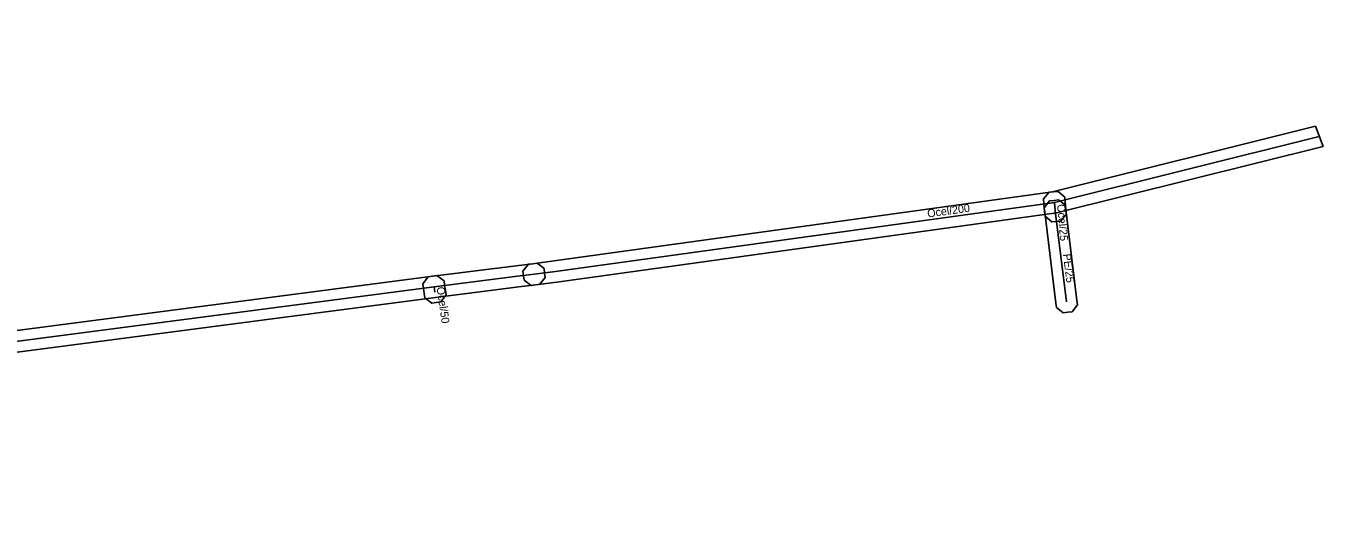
# Model space of a CAD drawing. Extents: x -866668 to -866425, y -1041329 to -1040263.
# Drawn here: x -866546.2 to -866424.6, y -1040308.7 to -1040263.2 of the extents above; entities that cross this region are included whole.
import ezdxf

# ---------------------------------------------------------------- set-up
doc = ezdxf.new("R2010")
doc.units = 0
for name, color, linetype in [('1', 7, 'Continuous'), ('24', 7, 'Continuous'), ('30', 7, 'Continuous')]:
    doc.layers.add(name, color=color, linetype=linetype)

msp = doc.modelspace()

# ---------------------------------------------------------------- linework, layer by layer
at = {"layer": '1'}
for points in [[(-866449.99, -1040278.77), (-866425.36, -1040272.63), (-866424.65, -1040274.51), (-866449.61, -1040280.73), (-866496.43, -1040287.21), (-866498.43, -1040287.47), (-866498.84, -1040287.53), (-866499.5, -1040287.02), (-866499.55, -1040286.61), (-866499.6, -1040286.2), (-866499.1, -1040285.54), (-866498.69, -1040285.49), (-866496.69, -1040285.23)], [(-866448.84, -1040279.25), (-866448.8, -1040279.66), (-866448.73, -1040280.46), (-866448.7, -1040280.88), (-866449.23, -1040281.51), (-866449.64, -1040281.55), (-866450.06, -1040281.58), (-866450.69, -1040281.05), (-866450.73, -1040280.64), (-866450.8, -1040279.84), (-866450.83, -1040279.42), (-866450.3, -1040278.79), (-866449.89, -1040278.75), (-866449.47, -1040278.72)], [(-866448.79, -1040280.02), (-866448.74, -1040280.43), (-866447.7, -1040288.93), (-866447.65, -1040289.34), (-866448.16, -1040289.99), (-866448.57, -1040290.04), (-866448.98, -1040290.09), (-866449.63, -1040289.58), (-866449.68, -1040289.17), (-866450.72, -1040280.67), (-866450.77, -1040280.26), (-866450.26, -1040279.61), (-866449.85, -1040279.56), (-866449.44, -1040279.51)], [(-866507, -1040287.1), (-866506.94, -1040287.51), (-866506.87, -1040288), (-866506.81, -1040288.41), (-866507.31, -1040289.07), (-866507.72, -1040289.13), (-866508.13, -1040289.19), (-866508.79, -1040288.69), (-866508.85, -1040288.28), (-866508.92, -1040287.79), (-866508.98, -1040287.38), (-866508.48, -1040286.72), (-866508.07, -1040286.66), (-866507.66, -1040286.6)]]:
    msp.add_lwpolyline(points, close=True, dxfattribs=at)
msp.add_lwpolyline([(-866554.46, -1040292.71), (-866508.06, -1040286.66), (-866500.23, -1040285.68), (-866498.68, -1040285.49), (-866498.27, -1040285.44), (-866497.62, -1040285.95), (-866497.57, -1040286.36), (-866497.52, -1040286.77), (-866498.03, -1040287.42), (-866498.44, -1040287.47), (-866499.99, -1040287.66), (-866507.8, -1040288.64), (-866554.18, -1040294.69)], dxfattribs=at)
at = {"layer": '24'}
for points in [[(-866666.69, -1040263.24), (-866663.99, -1040273.48), (-866661.45, -1040286.48), (-866658.78, -1040301.14), (-866658.53, -1040302.76), (-866658.53, -1040302.79), (-866657.84, -1040307.22), (-866657.82, -1040307.35), (-866657.61, -1040308.73), (-866640.8, -1040308.02), (-866630.1, -1040304.48), (-866626.37, -1040304.06), (-866597.03, -1040299.83), (-866563.76, -1040295.09), (-866554.32, -1040293.7), (-866507.93, -1040287.65), (-866500.11, -1040286.67), (-866498.56, -1040286.48)], [(-866498.56, -1040286.48), (-866496.56, -1040286.22), (-866449.8, -1040279.75), (-866425, -1040273.57)], [(-866449.8, -1040279.75), (-866449.73, -1040280.55)], [(-866449.73, -1040280.55), (-866448.69, -1040289.05)], [(-866507.93, -1040287.65), (-866507.86, -1040288.14)]]:
    msp.add_lwpolyline(points, dxfattribs=at)

# ---------------------------------------------------------------- texts
at = {"layer": '30'}
for s, rotation, p in [('Ocel/200', 7.8778, (-866461.67, -1040281.17)), ('Ocel/25', 275.0006, (-866449.57, -1040279.95)), ('PE/25', 276.9756, (-866449.01, -1040284.6)), ('Ocel/50', 278.1301, (-866507.7, -1040287.7))]:
    msp.add_text(s, height=0.75, rotation=rotation, dxfattribs=at).set_placement(p)

doc.saveas('drawing.dxf')
